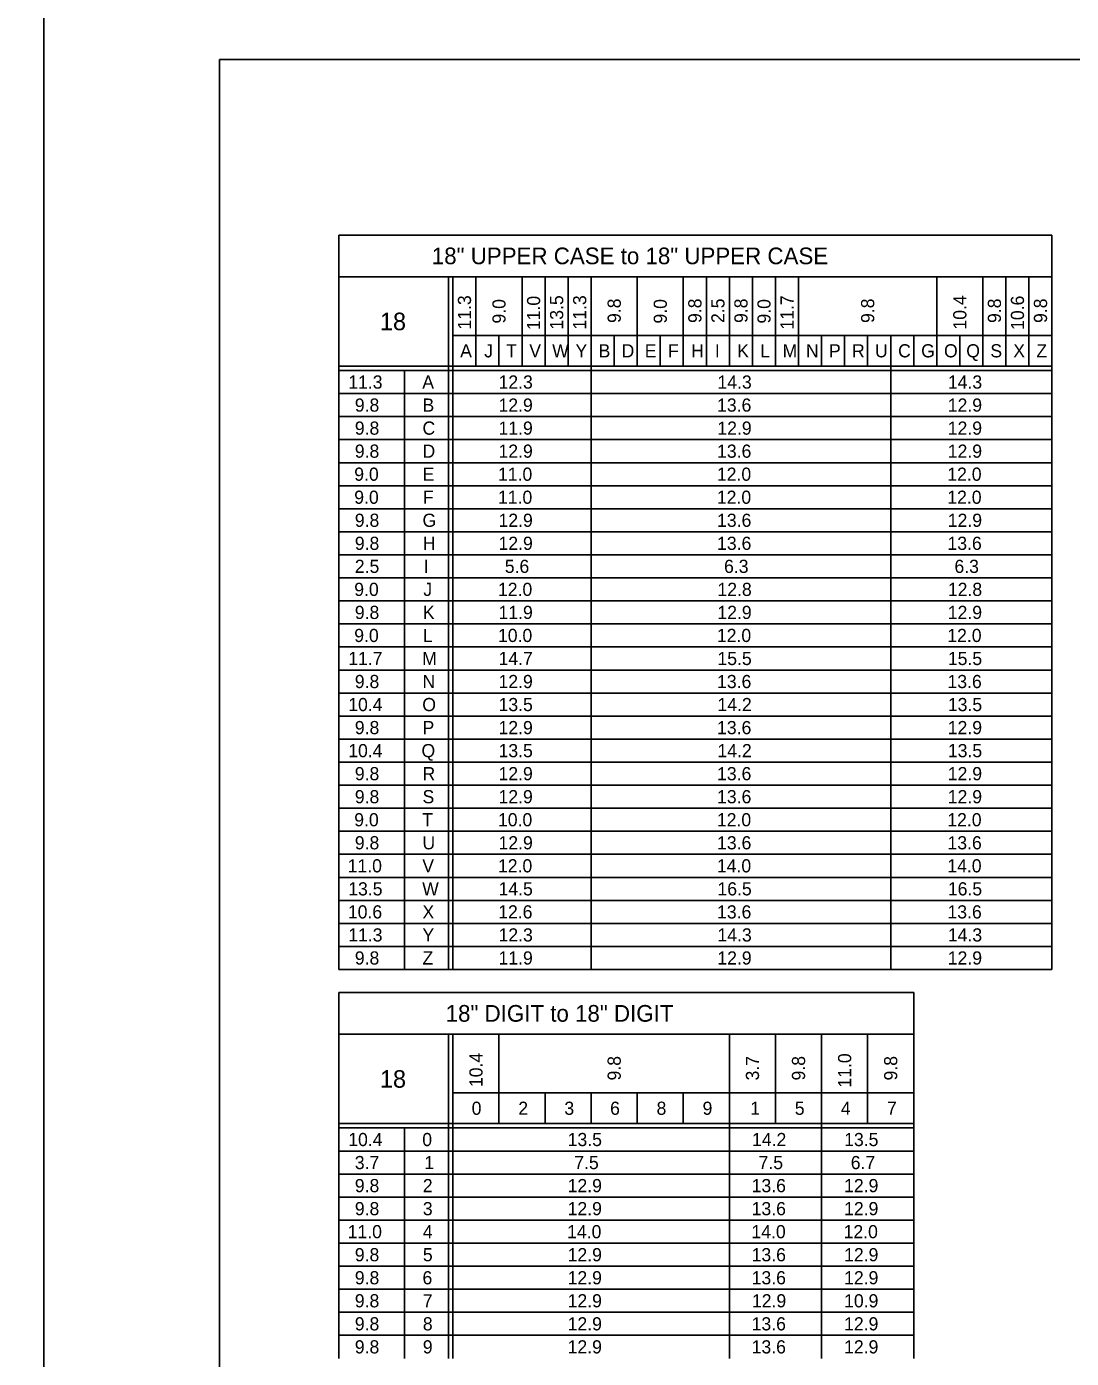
# Model space of a CAD drawing. Extents: x 637580 to 641849, y 297270 to 299646.
# Drawn here: x 640099.4 to 640337.4, y 297552.6 to 297856.1 of the extents above; entities that cross this region are included whole.
import ezdxf

# ---------------------------------------------------------------- set-up
doc = ezdxf.new("R2010")
doc.units = 0
for name, color, linetype in [('1', 7, 'Continuous'), ('2', 7, 'Continuous'), ('XCS-GRID-HVGL', 7, 'Continuous')]:
    doc.layers.add(name, color=color, linetype=linetype)

msp = doc.modelspace()

# ---------------------------------------------------------------- linework, layer by layer
at = {"layer": '1'}
for q in [(640929.31, 297848.63), (640143.31, 297284.63)]:
    msp.add_line((640143.31, 297848.63), q, dxfattribs=at)
at = {"layer": '2'}
for p, q in [((640333.01, 297808.63), (640170.51, 297808.63)), ((640170.51, 297808.63), (640170.51, 297641.25)), ((640333.01, 297808.63), (640333.01, 297641.25)), ((640170.51, 297799.13), (640333.01, 297799.13)), ((640195.51, 297799.13), (640195.51, 297641.25)), ((640196.51, 297799.13), (640196.51, 297641.25)), ((640201.76, 297799.13), (640201.76, 297778.75)), ((640212.26, 297799.13), (640212.26, 297778.75)), ((640217.51, 297799.13), (640217.51, 297778.75)), ((640222.76, 297799.13), (640222.76, 297778.75)), ((640228.01, 297799.13), (640228.01, 297641.25)), ((640238.51, 297799.13), (640238.51, 297778.75)), ((640249.01, 297799.13), (640249.01, 297778.75)), ((640254.26, 297799.13), (640254.26, 297778.75)), ((640259.51, 297799.13), (640259.51, 297778.75)), ((640264.76, 297799.13), (640264.76, 297778.75)), ((640270.01, 297799.13), (640270.01, 297778.75)), ((640275.26, 297799.13), (640275.26, 297778.75)), ((640306.76, 297799.13), (640306.76, 297778.75)), ((640317.26, 297799.13), (640317.26, 297778.75)), ((640322.51, 297799.13), (640322.51, 297778.75)), ((640327.76, 297799.13), (640327.76, 297778.75)), ((640196.51, 297785.75), (640333.01, 297785.75)), ((640207.01, 297785.75), (640207.01, 297778.75)), ((640233.26, 297785.75), (640233.26, 297778.75)), ((640243.76, 297785.75), (640243.76, 297778.75)), ((640280.51, 297785.75), (640280.51, 297778.75)), ((640285.76, 297785.75), (640285.76, 297778.75)), ((640291.01, 297785.75), (640291.01, 297778.75)), ((640291.01, 297785.75), (640291.01, 297778.75)), ((640296.26, 297785.75), (640296.26, 297641.25)), ((640301.51, 297785.75), (640301.51, 297778.75)), ((640312.01, 297785.75), (640312.01, 297778.75)), ((640333.01, 297778.75), (640170.51, 297778.75)), ((640333.01, 297777.75), (640170.51, 297777.75)), ((640185.51, 297777.75), (640185.51, 297641.25)), ((640333.01, 297772.5), (640170.51, 297772.5)), ((640333.01, 297767.25), (640170.51, 297767.25)), ((640333.01, 297762), (640170.51, 297762)), ((640333.01, 297756.75), (640170.51, 297756.75)), ((640333.01, 297751.5), (640170.51, 297751.5)), ((640333.01, 297746.25), (640170.51, 297746.25)), ((640333.01, 297741), (640170.51, 297741)), ((640333.01, 297735.75), (640170.51, 297735.75)), ((640333.01, 297730.5), (640170.51, 297730.5)), ((640333.01, 297725.25), (640170.51, 297725.25)), ((640333.01, 297720), (640170.51, 297720)), ((640333.01, 297714.75), (640170.51, 297714.75)), ((640333.01, 297709.5), (640170.51, 297709.5)), ((640333.01, 297704.25), (640170.51, 297704.25)), ((640333.01, 297699), (640170.51, 297699)), ((640333.01, 297693.75), (640170.51, 297693.75)), ((640333.01, 297688.5), (640170.51, 297688.5)), ((640333.01, 297683.25), (640170.51, 297683.25)), ((640333.01, 297678), (640170.51, 297678)), ((640333.01, 297672.75), (640170.51, 297672.75)), ((640333.01, 297667.5), (640170.51, 297667.5)), ((640333.01, 297662.25), (640170.51, 297662.25)), ((640333.01, 297657), (640170.51, 297657)), ((640333.01, 297651.75), (640170.51, 297651.75)), ((640333.01, 297646.5), (640170.51, 297646.5)), ((640170.51, 297641.25), (640170.51, 297641.25)), ((640170.51, 297641.25), (640333.01, 297641.25)), ((640301.51, 297636), (640170.51, 297636)), ((640170.51, 297636), (640170.51, 297552.63)), ((640301.51, 297552.63), (640301.51, 297636)), ((640170.51, 297626.5), (640301.51, 297626.5)), ((640195.51, 297626.5), (640195.51, 297552.63)), ((640196.51, 297626.5), (640196.51, 297552.63)), ((640207.01, 297626.5), (640207.01, 297606.13)), ((640259.51, 297626.5), (640259.51, 297552.63)), ((640270.01, 297626.5), (640270.01, 297606.13)), ((640280.51, 297626.5), (640280.51, 297552.63)), ((640291.01, 297626.5), (640291.01, 297606.13)), ((640196.51, 297613.13), (640301.51, 297613.13)), ((640217.51, 297613.13), (640217.51, 297606.13)), ((640228.01, 297613.13), (640228.01, 297606.13)), ((640238.51, 297613.13), (640238.51, 297606.13)), ((640249.01, 297613.13), (640249.01, 297606.13)), ((640301.51, 297606.13), (640170.51, 297606.13)), ((640301.51, 297605.13), (640170.51, 297605.13)), ((640185.51, 297605.13), (640185.51, 297552.63)), ((640301.51, 297599.88), (640170.51, 297599.88)), ((640301.51, 297594.63), (640170.51, 297594.63)), ((640301.51, 297589.38), (640170.51, 297589.38)), ((640301.51, 297584.13), (640170.51, 297584.13)), ((640301.51, 297578.88), (640170.51, 297578.88)), ((640301.51, 297573.63), (640170.51, 297573.63)), ((640301.51, 297568.38), (640170.51, 297568.38)), ((640301.51, 297563.13), (640170.51, 297563.13)), ((640301.51, 297557.88), (640170.51, 297557.88))]:
    msp.add_line(p, q, dxfattribs=at)
at = {"layer": 'XCS-GRID-HVGL'}
for points in [[(639262.31, 297863.63), (640103.31, 297863.63), (640103.31, 297269.63), (639262.31, 297269.63)], [(640103.31, 297863.63), (640944.31, 297863.63), (640944.31, 297269.63), (640103.31, 297269.63)]]:
    msp.add_lwpolyline(points, close=True, dxfattribs=at)

# ---------------------------------------------------------------- texts
at = {"layer": '2'}
for s, height, p in [('18" UPPER CASE to 18" UPPER CASE', 3.8, (640191.7, 297801.98)), ('18', 4, (640179.88, 297786.94)), ('A', 3, (640198.16, 297780.75)), ('J', 3, (640203.64, 297780.75)), ('T', 3, (640208.64, 297780.75)), ('V', 3, (640213.91, 297780.75)), ('W', 3, (640219.13, 297780.75)), ('Y', 3, (640224.44, 297780.75)), ('B', 3, (640229.7, 297780.75)), ('D', 3, (640234.95, 297780.75)), ('E', 3, (640240.22, 297780.75)), ('F', 3, (640245.52, 297780.75)), ('H', 3, (640250.79, 297780.75)), ('I', 3, (640256.2, 297780.75)), ('K', 3, (640261.29, 297780.75)), ('L', 3, (640266.54, 297780.75)), ('M', 3, (640271.63, 297780.75)), ('N', 3, (640276.95, 297780.75)), ('P', 3, (640282.2, 297780.75)), ('R', 3, (640287.45, 297780.75)), ('U', 3, (640292.69, 297780.75)), ('C', 3, (640297.95, 297780.75)), ('G', 3, (640303.2, 297780.75)), ('O', 3, (640308.41, 297780.75)), ('Q', 3, (640313.48, 297780.75)), ('S', 3, (640318.97, 297780.75)), ('X', 3, (640324.19, 297780.75)), ('Z', 3, (640329.45, 297780.75)), ('11.3', 3, (640172.66, 297773.63)), ('A', 3, (640189.53, 297773.63)), ('12.3', 3, (640206.91, 297773.63)), ('14.3', 3, (640256.79, 297773.63)), ('14.3', 3, (640309.29, 297773.63)), ('9.8', 3, (640174.16, 297768.38)), ('B', 3, (640189.58, 297768.38)), ('12.9', 3, (640206.9, 297768.38)), ('13.6', 3, (640256.7, 297768.38)), ('12.9', 3, (640309.27, 297768.38)), ('9.8', 3, (640174.16, 297763.13)), ('C', 3, (640189.58, 297763.13)), ('11.9', 3, (640206.9, 297763.13)), ('12.9', 3, (640256.77, 297763.13)), ('12.9', 3, (640309.27, 297763.13)), ('9.8', 3, (640174.16, 297757.88)), ('12.9', 3, (640206.9, 297757.88)), ('13.6', 3, (640256.7, 297757.88)), ('12.9', 3, (640309.27, 297757.88)), ('D', 3, (640189.58, 297757.88)), ('9.0', 3, (640174.03, 297752.63)), ('E', 3, (640189.59, 297752.63)), ('11.0', 3, (640206.78, 297752.63)), ('12.0', 3, (640256.66, 297752.63)), ('12.0', 3, (640309.16, 297752.63)), ('9.0', 3, (640174.03, 297747.38)), ('F', 3, (640189.65, 297747.38)), ('11.0', 3, (640206.78, 297747.38)), ('12.0', 3, (640256.66, 297747.38)), ('12.0', 3, (640309.16, 297747.38)), ('9.8', 3, (640174.16, 297742.13)), ('G', 3, (640189.58, 297742.13)), ('12.9', 3, (640206.9, 297742.13)), ('13.6', 3, (640256.7, 297742.13)), ('12.9', 3, (640309.27, 297742.13)), ('9.8', 3, (640174.16, 297736.88)), ('H', 3, (640189.66, 297736.88)), ('12.9', 3, (640206.9, 297736.88)), ('13.6', 3, (640256.7, 297736.88)), ('13.6', 3, (640309.2, 297736.88)), ('2.5', 3, (640174.16, 297731.63)), ('I', 3, (640189.83, 297731.63)), ('5.6', 3, (640208.33, 297731.63)), ('6.3', 3, (640258.29, 297731.63)), ('6.3', 3, (640310.79, 297731.63)), ('9.0', 3, (640174.03, 297726.38)), ('J', 3, (640189.77, 297726.38)), ('12.0', 3, (640206.78, 297726.38)), ('12.8', 3, (640256.79, 297726.38)), ('12.8', 3, (640309.29, 297726.38)), ('9.8', 3, (640174.16, 297721.13)), ('K', 3, (640189.66, 297721.13)), ('11.9', 3, (640206.9, 297721.13)), ('12.9', 3, (640256.77, 297721.13)), ('12.9', 3, (640309.27, 297721.13)), ('9.0', 3, (640174.03, 297715.88)), ('L', 3, (640189.66, 297715.88)), ('10.0', 3, (640206.78, 297715.88)), ('12.0', 3, (640256.66, 297715.88)), ('12.0', 3, (640309.16, 297715.88)), ('11.7', 3, (640172.66, 297710.63)), ('M', 3, (640189.51, 297710.63)), ('14.7', 3, (640206.91, 297710.63)), ('15.5', 3, (640256.79, 297710.63)), ('15.5', 3, (640309.29, 297710.63)), ('9.8', 3, (640174.16, 297705.38)), ('N', 3, (640189.58, 297705.38)), ('12.9', 3, (640206.9, 297705.38)), ('13.6', 3, (640256.7, 297705.38)), ('13.6', 3, (640309.2, 297705.38)), ('10.4', 3, (640172.66, 297700.13)), ('O', 3, (640189.53, 297700.13)), ('13.5', 3, (640206.91, 297700.13)), ('14.2', 3, (640256.79, 297700.13)), ('13.5', 3, (640309.29, 297700.13)), ('9.8', 3, (640174.16, 297694.88)), ('P', 3, (640189.58, 297694.88)), ('12.9', 3, (640206.9, 297694.88)), ('13.6', 3, (640256.7, 297694.88)), ('12.9', 3, (640309.27, 297694.88)), ('10.4', 3, (640172.66, 297689.63)), ('Q', 3, (640189.35, 297689.63)), ('13.5', 3, (640206.91, 297689.63)), ('14.2', 3, (640256.79, 297689.63)), ('13.5', 3, (640309.29, 297689.63)), ('9.8', 3, (640174.16, 297684.38)), ('R', 3, (640189.58, 297684.38)), ('12.9', 3, (640206.9, 297684.38)), ('13.6', 3, (640256.7, 297684.38)), ('12.9', 3, (640309.27, 297684.38)), ('9.8', 3, (640174.16, 297679.13)), ('S', 3, (640189.59, 297679.13)), ('12.9', 3, (640206.9, 297679.13)), ('13.6', 3, (640256.7, 297679.13)), ('12.9', 3, (640309.27, 297679.13)), ('9.0', 3, (640174.03, 297673.88)), ('T', 3, (640189.52, 297673.88)), ('10.0', 3, (640206.78, 297673.88)), ('12.0', 3, (640256.66, 297673.88)), ('12.0', 3, (640309.16, 297673.88)), ('9.8', 3, (640174.16, 297668.63)), ('U', 3, (640189.57, 297668.63)), ('12.9', 3, (640206.9, 297668.63)), ('13.6', 3, (640256.7, 297668.63)), ('13.6', 3, (640309.2, 297668.63)), ('11.0', 3, (640172.53, 297663.38)), ('V', 3, (640189.53, 297663.38)), ('12.0', 3, (640206.78, 297663.38)), ('14.0', 3, (640256.66, 297663.38)), ('14.0', 3, (640309.16, 297663.38)), ('13.5', 3, (640172.66, 297658.13)), ('W', 3, (640189.51, 297658.13)), ('14.5', 3, (640206.91, 297658.13)), ('16.5', 3, (640256.79, 297658.13)), ('16.5', 3, (640309.29, 297658.13)), ('10.6', 3, (640172.58, 297652.88)), ('X', 3, (640189.57, 297652.88)), ('12.6', 3, (640206.83, 297652.88)), ('13.6', 3, (640256.7, 297652.88)), ('13.6', 3, (640309.2, 297652.88)), ('11.3', 3, (640172.66, 297647.63)), ('Y', 3, (640189.57, 297647.63)), ('12.3', 3, (640206.91, 297647.63)), ('14.3', 3, (640256.79, 297647.63)), ('14.3', 3, (640309.29, 297647.63)), ('9.8', 3, (640174.16, 297642.38)), ('Z', 3, (640189.58, 297642.38)), ('11.9', 3, (640206.9, 297642.38)), ('12.9', 3, (640256.77, 297642.38)), ('12.9', 3, (640309.27, 297642.38)), ('18" DIGIT to 18" DIGIT', 3.8, (640194.86, 297629.35)), ('18', 4, (640179.88, 297614.31)), ('0', 3, (640200.78, 297608.13)), ('2', 3, (640211.41, 297608.13)), ('3', 3, (640221.91, 297608.13)), ('6', 3, (640232.33, 297608.13)), ('8', 3, (640242.91, 297608.13)), ('9', 3, (640253.4, 297608.13)), ('1', 3, (640264.25, 297608.13)), ('5', 3, (640274.41, 297608.13)), ('4', 3, (640284.91, 297608.13)), ('7', 3, (640295.41, 297608.13)), ('10.4', 3, (640172.66, 297601)), ('0', 3, (640189.53, 297601)), ('13.5', 3, (640222.66, 297601)), ('14.2', 3, (640264.66, 297601)), ('13.5', 3, (640285.66, 297601)), ('3.7', 3, (640174.16, 297595.75)), ('1', 3, (640190, 297595.75)), ('7.5', 3, (640224.16, 297595.75)), ('7.5', 3, (640266.16, 297595.75)), ('6.7', 3, (640287.16, 297595.75)), ('9.8', 3, (640174.16, 297590.5)), ('2', 3, (640189.66, 297590.5)), ('12.9', 3, (640222.65, 297590.5)), ('13.6', 3, (640264.58, 297590.5)), ('12.9', 3, (640285.65, 297590.5)), ('9.8', 3, (640174.16, 297585.25)), ('3', 3, (640189.66, 297585.25)), ('12.9', 3, (640222.65, 297585.25)), ('13.6', 3, (640264.58, 297585.25)), ('12.9', 3, (640285.65, 297585.25)), ('11.0', 3, (640172.53, 297580)), ('4', 3, (640189.66, 297580)), ('14.0', 3, (640222.53, 297580)), ('14.0', 3, (640264.53, 297580)), ('12.0', 3, (640285.53, 297580)), ('9.8', 3, (640174.16, 297574.75)), ('5', 3, (640189.66, 297574.75)), ('12.9', 3, (640222.65, 297574.75)), ('13.6', 3, (640264.58, 297574.75)), ('12.9', 3, (640285.65, 297574.75)), ('9.8', 3, (640174.16, 297569.5)), ('6', 3, (640189.58, 297569.5)), ('12.9', 3, (640222.65, 297569.5)), ('13.6', 3, (640264.58, 297569.5)), ('12.9', 3, (640285.65, 297569.5)), ('9.8', 3, (640174.16, 297564.25)), ('7', 3, (640189.66, 297564.25)), ('12.9', 3, (640222.65, 297564.25)), ('12.9', 3, (640264.65, 297564.25)), ('10.9', 3, (640285.65, 297564.25)), ('9.8', 3, (640174.16, 297559)), ('8', 3, (640189.66, 297559)), ('12.9', 3, (640222.65, 297559)), ('13.6', 3, (640264.58, 297559)), ('12.9', 3, (640285.65, 297559)), ('9.8', 3, (640174.16, 297553.75)), ('9', 3, (640189.65, 297553.75)), ('12.9', 3, (640222.65, 297553.75)), ('13.6', 3, (640264.58, 297553.75)), ('12.9', 3, (640285.65, 297553.75))]:
    msp.add_text(s, height=height, dxfattribs=at).set_placement(p)
for s, p in [('11.3', (640200.64, 297787.09)), ('11.0', (640216.39, 297786.96)), ('13.5', (640221.64, 297787.09)), ('11.3', (640226.89, 297787.09)), ('11.7', (640274.14, 297787.09)), ('10.4', (640313.51, 297787.09)), ('10.6', (640326.64, 297787.01)), ('9.0', (640208.51, 297788.46)), ('9.8', (640234.76, 297788.59)), ('9.0', (640245.26, 297788.46)), ('9.8', (640253.14, 297788.59)), ('2.5', (640258.39, 297788.59)), ('9.8', (640263.64, 297788.59)), ('9.0', (640268.89, 297788.46)), ('9.8', (640292.51, 297788.59)), ('9.8', (640321.39, 297788.59)), ('9.8', (640331.89, 297788.59)), ('10.4', (640203.26, 297614.46)), ('9.8', (640234.76, 297615.96)), ('3.7', (640266.26, 297615.96)), ('9.8', (640276.76, 297615.96)), ('11.0', (640287.26, 297614.33)), ('9.8', (640297.76, 297615.96))]:
    msp.add_text(s, height=3, rotation=90, dxfattribs=at).set_placement(p)

doc.saveas('drawing.dxf')
